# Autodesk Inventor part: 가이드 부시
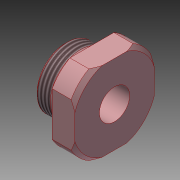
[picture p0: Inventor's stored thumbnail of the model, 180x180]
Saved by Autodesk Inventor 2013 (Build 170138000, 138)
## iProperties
Created: 2023-11
Part Number: 가이드 부시
Material: 강철, 탄소
Document SubType Name: Modeling
Designer: mdu-01
Density: 1 g/cm^3
Author: mdu-01
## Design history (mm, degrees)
sketch "스케치1"
  geometry: L1 (-7, 0)-(6, 0); L2 (-7, 5)-(-7, 8); L3 (-7, 8)-(-3, 8); L4 (-3, 8)-(-1.614, 7.2); L5 (-1.614, 7.2)-(0, 7.2); L6 (0, 7.2)-(0, 12); L7 (0, 12)-(5, 12); L8 (6, 11)-(6, 4); L9 (6, 4)-(-6, 4); L10 (-7, 5)-(-6, 4); L11 (5, 12)-(6, 11); 3 further points
  constraints: 22 end point, 8 point on line, 5 parallel, 2 perpendicular, 1 horizontal
  dimensions: "d0" = 6 distance between parallel lines of L8 L6; "d2" = 24 diameter of L7 L1; "d3" = 7 distance between parallel lines of L2 L6; "d4" = 8 diameter of L9 L1; "d5" = 16 diameter of L3 L1; "d6" = 14.4 diameter of L5 L1; "d7" = 3 distance from line of L3.end L6; "d8" = 30 deg angle of L3 L4; "d9" = 1 distance of L2.start point (-7, 4); "d10" = 1 distance of L9.end point (-7, 4) (= d9); "d11" = 1 distance of L7.end point (6, 12) (= d9); "d12" = 1 distance of L8.start point (6, 12) (= d11)
revolve "회전1" sketch "스케치1" stored, may be unused: angle "d13" = 90 deg
feature "스레드1" dims "d14" = 10, "d15" = 0
chamfer "모따기1" distance "d16" = 0.541; stored, may be unused: second distance "d17" = 2, angle "d18" = 45 deg
sketch "스케치2"
  geometry: L1 (10.5, -10.5)-(-10.5, -10.5); L2 (-10.5, -10.5)-(-10.5, 10.5); L3 (-10.5, 10.5)-(10.5, 10.5); L4 (10.5, 10.5)-(10.5, -10.5); L5 (10.5, -10.5)-(-10.5, 10.5); L6 (-10.5, -10.5)-(10.5, 10.5); 1 further point
  constraints: 12 end point, 2 midpoint, 2 parallel, 1 horizontal, 1 perpendicular
  dimensions: "d19" = 21 distance of L2.end L3.end; "d20" = 21 distance of L1.end L2.end
extrude "돌출1" sketch "스케치2" stored distance "d21" = 0; taper "d22" = 0 deg
node "솔리드1"
